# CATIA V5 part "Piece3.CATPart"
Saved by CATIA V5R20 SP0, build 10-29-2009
Part number: Piece3
Bounding box of the stored display mesh (mm): x 0 to 100, y 270.114 to 580, z -8.418 to 0
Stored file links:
  C:\Users\Lambert\Desktop\IAO\Piece3.CATPart
  C:\Users\Lambert\Desktop\IAO\Piece2.3.CATPart
  C:\Users\Lambert\Desktop\IAO\Produit1.CATProduct
  C:\Users\Lambert\Desktop\IAO\skl_general.CATPart
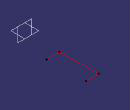
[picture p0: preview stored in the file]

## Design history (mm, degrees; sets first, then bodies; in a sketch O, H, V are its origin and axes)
Set1
  Point1 "G": linked copy from another document
  DatumPoint1 "F": linked copy from another document
  Plane1 "Plan_Ref": linked copy from another document
Set2
  Line1 "Bielle 3": type PtPt, FirstPoint Point1, SecondPoint DatumPoint1, Support Plane1
  Line2 "Axe_pivot_30": type Normal, RefPoint Point1, RefSkin Plane1, Start 0, End 100
  Line3 "Axe_pivot_34": type Normal, RefPoint DatumPoint1, RefSkin Plane1, Start 0, End 100
Body1 (main body)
